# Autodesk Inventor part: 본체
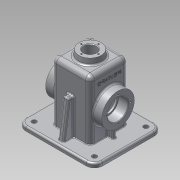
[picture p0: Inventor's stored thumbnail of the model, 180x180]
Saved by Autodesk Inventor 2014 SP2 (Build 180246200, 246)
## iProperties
Created: 2016-08
Part Number: 본체
Material: 알루미늄 6061
Document SubType Name: Modeling
Designer: user
Density: 2.71 g/cm^3
Appearance: 알루미늄 - 평지
Author: user
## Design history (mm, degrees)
sketch "스케치1"
  geometry: L1 (-32.5, -32.5)-(32.5, -32.5); L2 (32.5, -32.5)-(32.5, 32.5); L3 (32.5, 32.5)-(-32.5, 32.5); L4 (-32.5, 32.5)-(-32.5, -32.5); L5 (-32.5, -32.5)-(32.5, 32.5); L6 (32.5, -32.5)-(-32.5, 32.5); 1 further point
  constraints: 12 end point, 2 midpoint, 2 parallel, 1 horizontal, 1 perpendicular
  dimensions: "d0" = 65 distance of L3.end L2.end; "d1" = 65 distance of L2.end L1.end
extrude "돌출1" new body sketch "스케치1" stored distance "d2" = 100; taper "d3" = 0 deg
sketch "스케치2"
  geometry: L1 (65, 57.5)-(-65, 57.5); L2 (-65, 57.5)-(-65, -57.5); L3 (-65, -57.5)-(65, -57.5); L4 (65, -57.5)-(65, 57.5); L5 (65, 57.5)-(-65, -57.5); L6 (-65, 57.5)-(65, -57.5); 1 further point
  constraints: 12 end point, 2 midpoint, 2 parallel, 1 horizontal, 1 perpendicular
  dimensions: "d4" = 130 distance of L3.end L2.end; "d5" = 115 distance of L2.end L1.end
extrude "돌출2" join sketch "스케치2" distance "d6" = 7; taper "d7" = 0 deg
sketch "스케치3"
  geometry: L1 (-65, -57.5)-(65, -57.5) reference; L2 (65, -57.5)-(65, 57.5) reference; L3 (65, 57.5)-(-65, 57.5) reference; L4 (-65, 57.5)-(-65, -57.5) reference; L5 (60, -52.5)-(-60, -52.5); L6 (-60, -52.5)-(-60, 52.5); L7 (-60, 52.5)-(60, 52.5); L8 (60, 52.5)-(60, -52.5); 1 further point
  constraints: 8 end point, 3 other
  dimensions: "d8" = 5 distance between parallel lines of L1 L5
extrude "돌출3" join sketch "스케치3" distance "d9" = 3; taper "d10" = 0 deg
fillet "모깎기1" dims "d11" = 8
fillet "모깎기2" dims "d12" = 8
sketch "스케치4"
  geometry: L1 (10, 77)-(10, -28) reference; L2 (-92, -8)-(0, -8) reference; C1 r 27.5 at (-45, 24.5); 1 further point
  constraints: 1 centre point
  dimensions: "d13" = 55 distance from line of L1 C1.centre; "d14" = 55 diameter of C1; "d15" = 32.5 distance from line of L2 C1.centre
extrude "돌출4" join sketch "스케치4" distance "d16" = 15; taper "d17" = 0 deg
sketch "스케치5"
  geometry: L1 (60, -60)-(-60, -60) reference; L2 (27.5, -60)-(27.5, 42); L3 (24.5, 45)-(-24.5, 45); L4 (-27.5, 42)-(-27.5, -60); L5 (27.5, -60)-(-27.5, -60); L6 (32.5, 7.49)-(32.5, 42) reference; L7 (-32.5, 42)-(-32.5, 7.49) reference; L8 (24.5, 50)-(-24.5, 50) reference; A1 r 3 centre (24.5, 42) between (27.5, 42) and (24.5, 45); A2 r 3 centre (-24.5, 42) between (-24.5, 45) and (-27.5, 42); 1 further point
  constraints: 8 end point, 4 perpendicular, 4 point on circle, 4 tangent, 2 centre point, 2 point on line, 1 equal radius
  dimensions: "d18" = 5 distance between parallel lines of L6 L2; "d19" = 5 distance between parallel lines of L7 L4; "d20" = 5 distance between parallel lines of L3 L8; "d21" = 3 radius of A1
extrude "돌출5" cut sketch "스케치5" stored distance "d22" = 55; taper "d23" = 0 deg
fillet "모깎기3" dims "d24" = 3
sketch "스케치7"
  geometry: L1 (32.5, 42)-(32.5, -50) reference; L2 (-57.5, -50)-(57.5, -50) reference; L3 (57.5, -50)-(57.5, -57) reference; L4 (49.5, -50)-(41.068, 10); L5 (-52.5, -60)-(52.5, -60) reference; L6 (-49.5, -50)-(-41.068, 10); L7 (-57.5, -50)-(-57.5, -57) reference; L8 (41.068, 10)-(32.5, 10); 1 further point
  constraints: 6 end point, 3 point on line, 1 perpendicular
  dimensions: "d30" = 70 distance from line of L5 L4.end; "d31" = 8 deg angle of L3 L4; "d32" = 8 distance of L2.end L4.start; "d33" = 8 deg angle of L7 L6; "d34" = 70 distance from line of L5 L6.end; "d35" = 8 distance from line of L7 L6.start
feature "리브1" sketch "스케치7" dims "d36" = 1, "d37" = 10, "d38" = 0, "d39" = 0, "d40" = 1, "d41" = 1
sketch "스케치8"
  geometry: L1 (47.5, 22.5)-(47.5, -32.5) reference; L2 (47.5, -5)-(-47.5, -5); L3 (-47.5, 22.5)-(-47.5, -32.5) reference; L4 (47.5, -5)-(47.5, 12.5); L5 (47.5, 12.5)-(30.5, 12.5); L6 (30.5, 12.5)-(30.5, 10); L7 (30.5, 10)-(-30.5, 10); L8 (-30.5, 10)-(-30.5, 12.5); L9 (-30.5, 12.5)-(-47.5, 12.5); L10 (-47.5, 12.5)-(-47.5, -5); 1 further point
  constraints: 16 end point, 5 perpendicular, 2 midpoint, 2 parallel, 2 point on line
  dimensions: "d42" = 17 distance of L4.end L5.end; "d43" = 17 distance of L8.end L9.end; "d44" = 30 diameter of L7 L2; "d45" = 35 diameter of L9 L2; "d46" = 35 diameter of L5 L2
revolve "회전1" sketch "스케치8" stored, may be unused: angle "d47" = 90 deg
sketch "스케치9"
  geometry: C1 r 27.5 at (0, 0) reference; 2 further points
  constraints: 1 horizontal alignment
  dimensions: "d48" = 21 distance of C1.centre point (-21, 0)
hole "구멍1" sketch "스케치9" at (-21, 0) diameter "d49" = 3.242; stored, may be unused: countersink angle "d53" = 90 deg, drill point angle "d55" = 118 deg; dims "d50" = 8, "d51" = 4, "d52" = 2, "d54" = 10
fillet "모깎기4" dims "d59" = 14
fillet "모깎기5" dims "d60" = 9
hole "구멍2" diameter "d63" = 8; stored, may be unused: countersink angle "d67" = 90 deg, drill point angle "d69" = 118 deg; dims "d61" = 10, "d62" = 10, "d64" = 8, "d65" = 4, "d66" = 2, "d68" = 10
hole "구멍3" diameter "d72" = 8; stored, may be unused: countersink angle "d76" = 90 deg, drill point angle "d78" = 118 deg; dims "d70" = 10, "d71" = 10, "d73" = 8, "d74" = 4, "d75" = 2, "d77" = 10
hole "구멍4" diameter "d81" = 8; stored, may be unused: countersink angle "d85" = 90 deg, drill point angle "d87" = 118 deg; dims "d79" = 10, "d80" = 10, "d82" = 8, "d83" = 4, "d84" = 2, "d86" = 10
hole "구멍5" diameter "d90" = 8; stored, may be unused: countersink angle "d94" = 90 deg, drill point angle "d96" = 118 deg; dims "d88" = 10, "d89" = 10, "d91" = 8, "d92" = 4, "d93" = 2, "d95" = 10
sketch "스케치11"
  geometry: C1 r 20 at (0, 0); 1 further point
  constraints: 1 centre point, 1 coincident
  dimensions: "d97" = 40 diameter of C1
extrude "돌출7" join sketch "스케치11" distance "d98" = 10; taper "d99" = -7 deg
hole "구멍6" diameter "d102" = 21; stored, may be unused: countersink angle "d106" = 90 deg, drill point angle "d108" = 118 deg; dims "d100" = 10, "d101" = 10, "d103" = 8, "d104" = 4, "d105" = 2, "d107" = 10
sketch "스케치12"
  geometry: A1 r 14.5 centre (0, 0) between (0, 14.5) and (0, -14.5); 3 further points
  constraints: 4 point on circle, 2 horizontal alignment, 2 vertical alignment, 1 centre point, 1 coincident
  dimensions: "d109" = 29 diameter of A1
hole "구멍7" sketch "스케치12" at (0, 14.5), (0, -14.5), (14.5, 0), (-14.5, 0) diameter "d110" = 2.459; stored, may be unused: countersink angle "d114" = 90 deg, drill point angle "d116" = 118 deg; dims "d111" = 7, "d112" = 4, "d113" = 2, "d115" = 9
node "작업 평면1"
sketch "스케치13"
  geometry: L1 (0, -8)-(92, -8) reference; L2 (-18, 5.728)-(-18, 43.272) reference; 2 further points
  constraints: 1 other
  dimensions: "d119" = 26 distance from line of point (8, 24.5) L2; "d143" = 32.5 distance from line of L1 point (8, 24.5)
feature "엠보싱1" sketch "스케치13" dims "d120" = 0.5, "d121" = 0
fillet "모깎기6" dims "d122" = 3
fillet "모깎기7" dims "d123" = 3
fillet "모깎기10" dims "d126" = 3
chamfer "모따기1" distance "d127" = 1; stored, may be unused: second distance "d128" = 2, angle "d129" = 45 deg
fillet "모깎기11" dims "d130" = 0.3
sketch "스케치14"
  geometry: L1 (32.5, 3)-(42.5, 3); L2 (42.5, 3)-(42.5, -3); L3 (42.5, -3)-(32.5, -3); L4 (27.5, -24.5)-(27.5, 24.5) reference; L5 (32.5, 24.5)-(32.5, -24.5) reference; 2 further points
  constraints: 6 end point, 2 point on line, 1 horizontal, 1 horizontal alignment, 1 midpoint, 1 parallel, 1 perpendicular
  dimensions: "d132" = 6 distance of L1.end L2.end; "d133" = 15 horizontal distance of L4.end point (42.5, 0)
extrude "돌출8" join sketch "스케치14" stored distance "d134" = 10; taper "d135" = 0 deg
fillet "모깎기12" dims "d136" = 3
fillet "모깎기13" dims "d137" = 3
fillet "모깎기14" dims "d138" = 3
fillet "모깎기15" dims "d139" = 3
fillet "모깎기17" dims "d141" = 3
fillet "모깎기18" dims "d142" = 1
node "솔리드1"
mirror "대칭1"
mirror "대칭2"
mirror "대칭4"
pattern_circular "원형 패턴1" dims angle "d57" = 360 deg
mirror "대칭5"
mirror "대칭6"
other parameters: "d117" = 49.25
